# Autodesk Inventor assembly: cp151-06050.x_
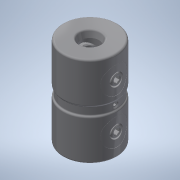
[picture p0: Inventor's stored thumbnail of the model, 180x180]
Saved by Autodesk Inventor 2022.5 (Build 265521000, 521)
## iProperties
Part Number: cp151-06050.x_
Material: 一般
Document SubType Name: Assembly
Designer: ImaoCorp
Sending System: SOLIDWORKS 2017-2017317
MC: AMD64
MC_MODEL: Intel64 Family 6 Model 60 Stepping 3, GenuineIntel
OS: Windows_NT
FRU: Parasolid Version 29.0, build 201,  4-17-2017
FORMAT: text
GUISE: transmit
KEY: cp151-06050
FILE: cp151-06050.x_t
DATE: Wed Sep 25 13:52:16 2019
Author: ImaoCorp
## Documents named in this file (8)
- X:\14_SW2022-Inv2022\00_全2023-1023新製品(TCC)まで\c\cp151-06050\CP151-06050.iam
- X:\14_SW2022-Inv2022\00_全2023-1023新製品(TCC)まで\c\cp151-06050\cp151-06050_01.ipt
- X:\14_SW2022-Inv2022\00_全2023-1023新製品(TCC)まで\c\cp151-06050\cp151-06050_02.ipt
- X:\14_SW2022-Inv2022\00_全2023-1023新製品(TCC)まで\c\cp151-06050\cp151-06050_03.ipt
- X:\14_SW2022-Inv2022\00_全2023-1023新製品(TCC)まで\c\cp151-06050\cp151-06050_04.ipt
- X:\14_SW2022-Inv2022\00_全2023-1023新製品(TCC)まで\c\cp151-06050\cp151-06050_05.ipt
- X:\14_SW2022-Inv2022\00_全2023-1023新製品(TCC)まで\c\cp151-06050\cp151-06050_06.ipt
- X:\14_SW2022-Inv2022\00_全2023-1023新製品(TCC)まで\c\cp151-06050\cp151-06050_07.ipt
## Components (7 placed, 7 different names)
1. cp151-06050_01
2. cp151-06050_02
3. cp151-06050_03
4. cp151-06050_04
5. cp151-06050_05
6. cp151-06050_06
7. cp151-06050_07
